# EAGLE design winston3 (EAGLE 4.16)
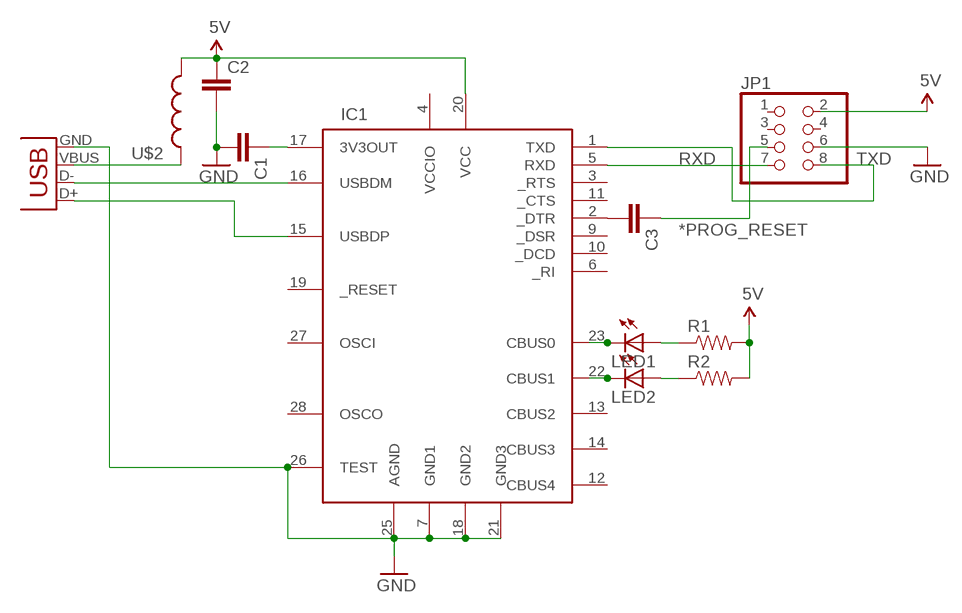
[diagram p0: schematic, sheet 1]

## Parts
C1  CAP0603  [0603]
C2  CAP0603  [0603]
C3  CAP0603  [0603]
IC1  FT232RL  [SSOP28DB]
JP1  PINHD-2X4  [2X04]
LED1  LED5MM  [LED5MM]
LED2  LED5MM  [LED5MM]
R1  RESISTOR  [0805]
R2  RESISTOR  [0805]
U$2  INDUCTOR0603  [0603]
X1  USBPTH  [USB-B-PTH]

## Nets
5V: C2.1 IC1.20(VCC) JP1.2 R1.2 R2.2 U$2.2
*PROG_RESET: C3.1 JP1.5
D+: IC1.15(USBDP) X1.D+
D-: IC1.16(USBDM) X1.D-
GND: C1.2 C2.2 IC1.7(GND1) IC1.18(GND2) IC1.21(GND3) IC1.25(AGND) IC1.26(TEST) JP1.6 X1.GND
N$1: LED1.A R1.1
N$2: LED2.A R2.1
N$3: U$2.1 X1.VBUS
N$6: IC1.23(CBUS0) LED1.K(C)
N$7: IC1.22(CBUS1) LED2.K(C)
N$12: C3.2 IC1.2(_DTR)
RXD: IC1.5(RXD) JP1.7
TXD: IC1.1(TXD) JP1.8
V3.3: C1.1 IC1.17(3V3OUT)
Unconnected: IC1.3(_RTS) IC1.6(_RI) IC1.9(_DSR) IC1.10(_DCD) IC1.11(_CTS) IC1.12(CBUS4) IC1.13(CBUS2) IC1.14(CBUS3) IC1.19(_RESET) IC1.27(OSCI) IC1.28(OSCO) JP1.1 JP1.3 JP1.4

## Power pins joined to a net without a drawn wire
VCCIO: IC1.4(VCCIO)

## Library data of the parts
C1-C3 = SparkFun:CAP: Capacitor
IC1 = SparkFun:FT232RL: USB UART FT232RL 4th Generation USB UART (USB <-> Serial) Controller. Spark Fun Electronics SKU : COM-00650
JP1 = pinhead:PINHD-2X4: PIN HEADER
LED1 LED2 = SparkFun:LED: LEDs
R1 R2 = SparkFun:RESISTOR: Resistor
U$2 = SparkFun:INDUCTOR: Inductors
X1 = SparkFun:USB: USB Connectors USB-B-PTH is fully proven SKU : PRT-00139 USB-miniB is fully proven SKU : PRT-00587 USB-A-PCB is untested. USB-A-H is throughly reviewed, but untested. Spark Fun Electronics SKU : PRT-00437 USB-B-SMT is throughly reviewed, but untested. Needs silkscreen touching up. USB-A-S has not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

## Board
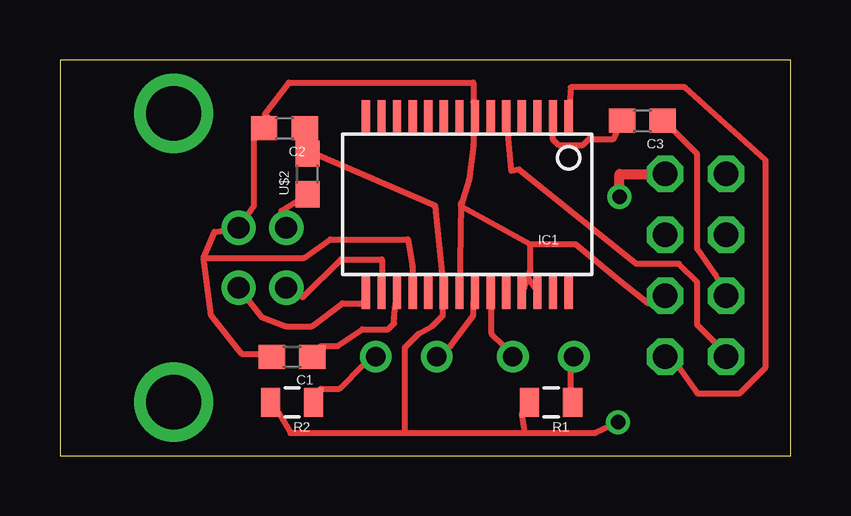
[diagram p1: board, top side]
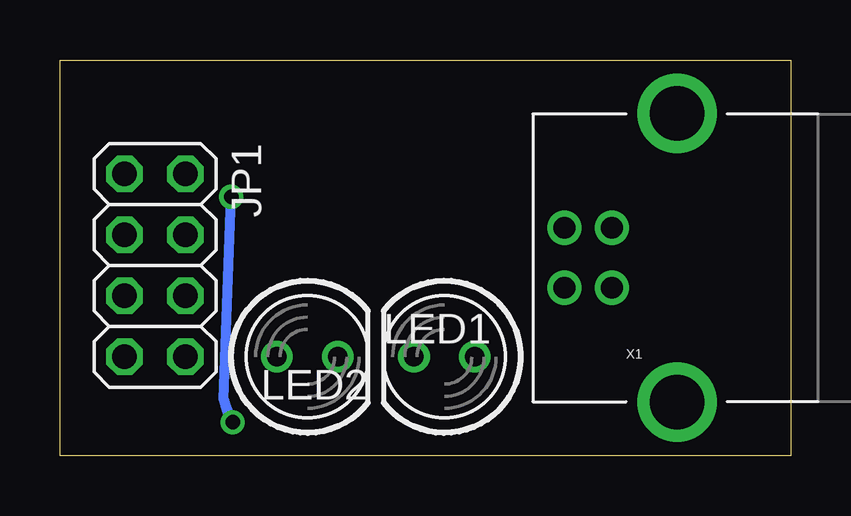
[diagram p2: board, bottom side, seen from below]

Size 30.47 x 16.5 mm. Coordinates in mm from the lower left corner, seen from the top.
Outline: 0,0 30.47,0 30.47,16.5 0,16.5 0,0
Copper layers (1*16): Top 0.035mm / dielectric 1.5mm / Bottom 0.035mm
Design rules "default": minimum track width 10mil, minimum drill 24mil, track to track 8mil, track to pad 8mil, pad to pad 8mil, via to via 8mil, smd to smd 8mil, copper to edge 40mil, drill to drill 8mil, minimum pad ring 10mil, minimum via ring 8mil, stop-mask expansion 4mil, vias tented up to drill 0mil, thermal gap 10mil

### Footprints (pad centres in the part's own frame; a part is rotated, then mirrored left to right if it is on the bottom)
0603 = smd 1.1 x 1: 1 -0.85,0; 2 0.85,0
SSOP28DB = smd 0.348 x 1.397: 1 -4.225,-3.656; 2 -3.575,-3.656; 3 -2.925,-3.656; 4 -2.275,-3.656; 5 -1.625,-3.656; 6 -0.975,-3.656; 7 -0.325,-3.656; 8 0.325,-3.656; 9 0.975,-3.656; 10 1.625,-3.656; 11 2.275,-3.656; 12 2.925,-3.656; 13 3.575,-3.656; 14 4.225,-3.656; 15 4.225,3.656; 16 3.575,3.656; 17 2.925,3.656; 18 2.275,3.656; 19 1.625,3.656; 20 0.975,3.656; 21 0.325,3.656; 22 -0.325,3.656; 23 -0.975,3.656; 24 -1.625,3.656; 25 -2.275,3.656; 26 -2.925,3.656; 27 -3.575,3.656; 28 -4.225,3.656
2X04 = drill 1.016 octagon: 1 -3.81,-1.27; 2 -3.81,1.27; 3 -1.27,-1.27; 4 -1.27,1.27; 5 1.27,-1.27; 6 1.27,1.27; 7 3.81,-1.27; 8 3.81,1.27
LED5MM = drill 0.813 round: A -1.27,0; K 1.27,0
0805 = smd 0.8 x 1.2: 1 -0.9,0; 2 0.9,0
USB-B-PTH = drill 0.914 round: D+ 0,1.25; D- 1.981,1.25; GND 0,-1.25; VBUS 1.981,-1.25 | drill 2.286 round: P$1 -2.718,-6.02; P$2 -2.718,6.02

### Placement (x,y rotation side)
C1  9.68,4.12 180 top
C2  9.36,13.65 180 top
C3  24.28,13.96 180 top
IC1  16.98,10.47 180 top
JP1  26.5,7.93 270 bottom
LED1  20.15,4.12 0 bottom
LED2  14.44,4.12 180 bottom
R1  20.47,2.22 180 top
R2  9.68,2.22 180 top
U$2  10.31,11.74 90 top
X1  7.46,8.25 180 bottom

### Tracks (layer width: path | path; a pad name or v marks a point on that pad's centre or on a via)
5V  (via drill 0.6)
  Top 0.254: U$2.2 10.38,12.44 10.38,13.2 C2.1 10.63,12.57 15.65,10.41 15.96,7.36 IC1.20 15.96,6.35 15.96,5.84 15.52,5.39 14.95,5.07 14.38,4.5 14.38,0.95 | 14.38,0.95 19.39,0.95 | 14.38,0.95 9.61,0.95 9.11,1.77 R2.2 | 19.39,0.95 19.27,1.77 R1.2 | v23.27,1.39 22.31,0.95 19.39,0.95
  Top 0.406: JP1.2 23.33,11.74 v23.33,10.79
  Bottom 0.406: 23.65,2.35 23.33,1.27 | v23.27,1.39 23.65,2.35 | 23.65,2.35 v23.33,10.79
*PROG_RESET
  Top 0.254: C3.1 25.3,13.84 26.57,12.57 26.57,8.63 27.33,7.55 JP1.5
D+
  Top 0.254: IC1.15 12.66,6.35 11.77,6.35 10.5,5.39 9.42,5.39 8.41,5.77 X1.D+
D-
  Top 0.254: IC1.16 13.42,7.36 13.42,8.19 11.71,8.19 10.12,6.6 X1.D-
GND
  Top 0.254: 5.99,8.25 6.31,5.84 7.58,4.25 8.34,4.25 C1.2 | 5.99,8.25 6.44,9.33 X1.GND 8.09,10.41 8.09,13.2 C2.2 8.85,13.96 8.54,14.22 9.55,15.55 17.23,15.55 17.23,14.73 IC1.7 17.23,13.46 17.23,12.95 17.04,11.49 16.73,10.41 | 5.99,8.25 10.19,8.25 11.27,9.01 14.5,9.01 14.69,7.87 14.69,7.36 IC1.18 | IC1.26 19.46,7.49 19.27,6.85 IC1.25 19.58,7.68 19.58,8.82 | 16.73,10.41 16.73,10.54 IC1.21 | 16.73,10.41 19.58,8.82 | 19.58,8.82 21.49,8.82 23.33,7.3 24.54,6.35 JP1.6
N$1
  Top 0.254: R1.1 21.3,2.79 21.3,3.55 LED1.A
N$2
  Top 0.254: R2.1 10.88,2.79 11.65,2.79 12.66,3.8 LED2.A
N$3
  Top 0.254: U$2.1 9.23,10.22 9.23,9.71 X1.VBUS
N$6
  Top 0.254: IC1.23 18,6.35 18,5.07 18.5,4.57 LED1.K
N$7
  Top 0.254: IC1.22 17.23,6.35 17.23,5.84 16.28,4.57 LED2.K
N$12
  Top 0.254: C3.2 23.08,13.2 22.06,13.2 21.81,12.95 20.79,12.95 20.54,13.2 20.54,13.46 IC1.2
RXD
  Top 0.254: IC1.5 18.82,11.87 19.14,11.93 24.03,8 25.81,8 26.57,7.23 26.57,5.46 27.33,4.69 JP1.7
TXD
  Top 0.254: IC1.1 21.3,15.36 26.06,15.36 29.43,12.31 29.43,3.68 28.35,2.6 26.57,2.6 25.81,3.68 JP1.8
V3.3
  Top 0.254: C1.1 10.88,4.57 11.58,4.57 12.6,5.27 13.68,5.27 13.93,5.52 13.93,5.71 IC1.17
